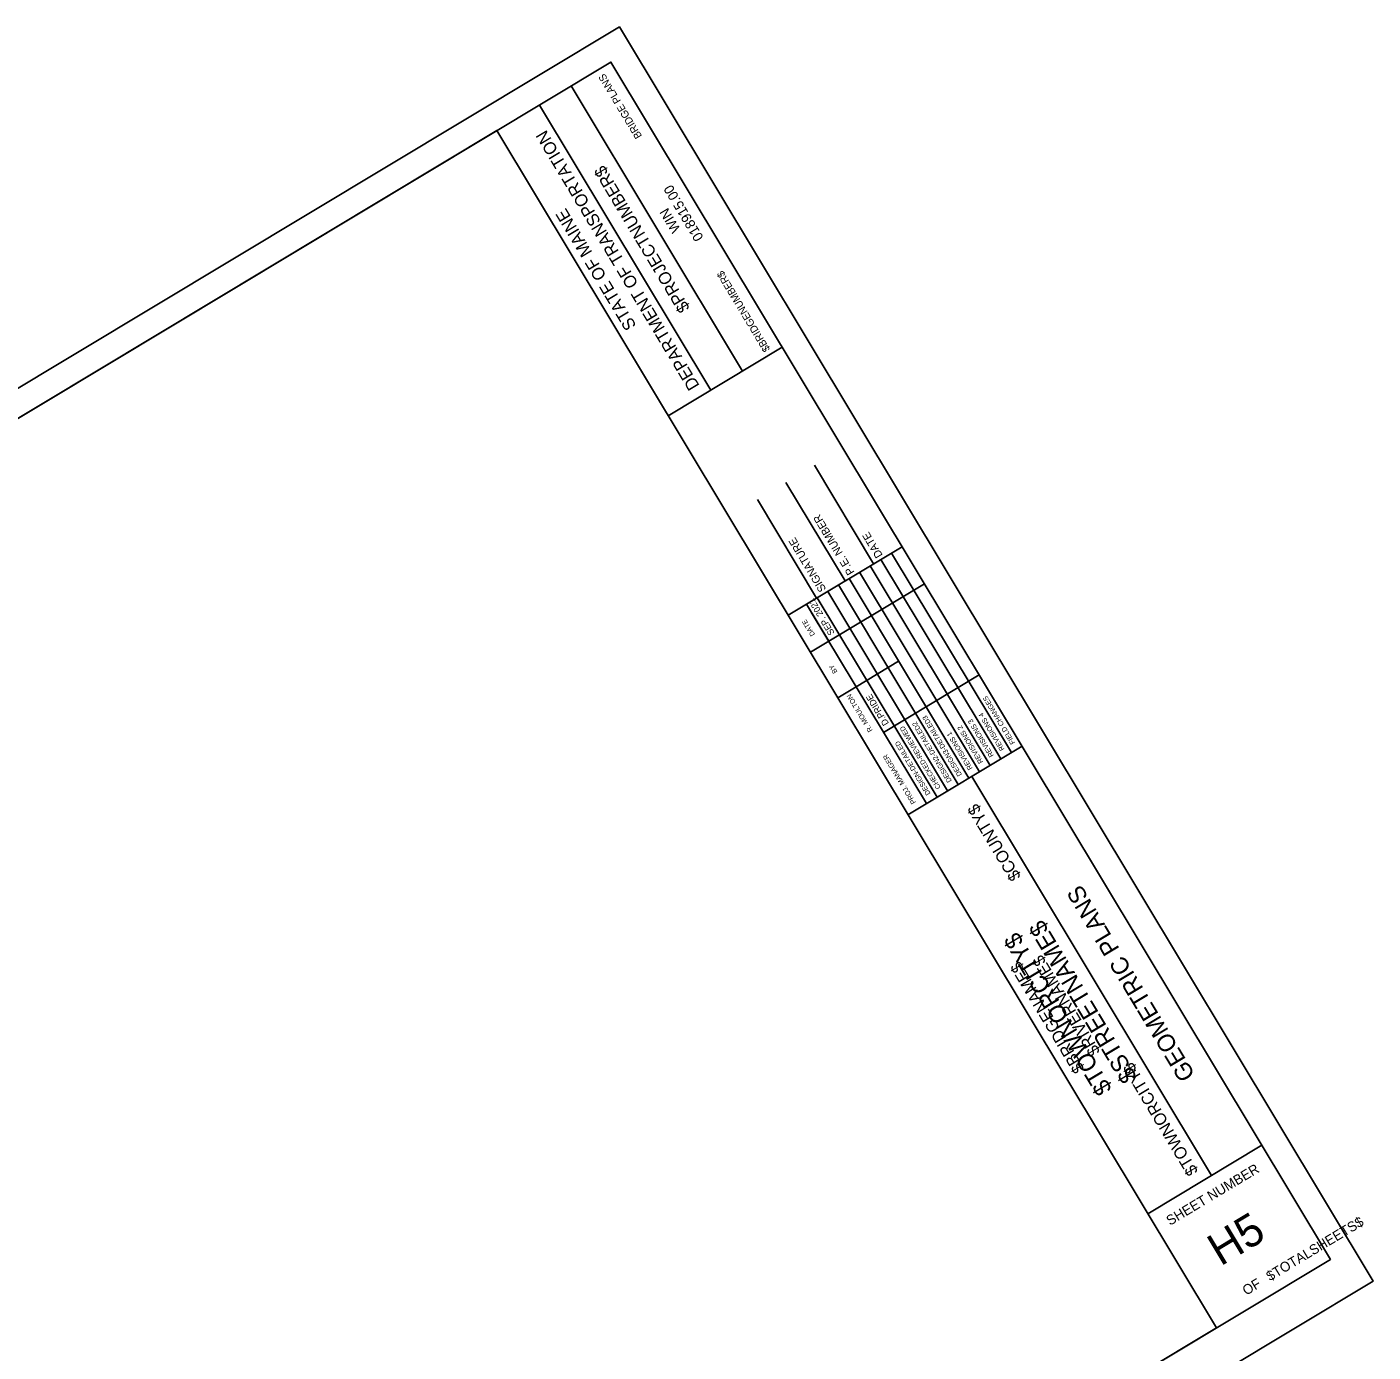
# Model space of a CAD drawing. Extents: x 1744490 to 1745501, y 462969 to 463878.
# Drawn here: x 1744996 to 1745501, y 463380 to 463878 of the extents above; entities that cross this region are included whole.
import ezdxf

# ---------------------------------------------------------------- set-up
doc = ezdxf.new("R2010")
doc.units = 0
for name, color, linetype in [('ANNOTATION', 7, 'Continuous'), ('D_Roadway_Centerline_Flags', 7, 'Continuous'), ('D_Roadway_Centerline_Text', 7, 'Continuous'), ('M_Fencing', 7, 'Continuous'), ('M_Misc_MiscItems', 7, 'Continuous')]:
    doc.layers.add(name, color=color, linetype=linetype)

msp = doc.modelspace()

# ---------------------------------------------------------------- linework, layer by layer
at = {"layer": 'D_Roadway_Centerline_Text'}
for p, q in [((1745264.5, 463749.09), (1745200.12, 463856.24)), ((1745252.52, 463741.9), (1745188.14, 463849.04)), ((1745442.55, 463389.44), (1745172.15, 463839.45)), ((1745236.55, 463732.28), (1745279.41, 463758.03)), ((1745313.73, 463676.63), (1745291.46, 463713.69)), ((1745303.02, 463670.19), (1745280.75, 463707.25)), ((1745292.3, 463663.76), (1745270.04, 463700.82)), ((1745281.59, 463657.32), (1745324.45, 463683.07)), ((1745326.66, 463582.32), (1745369.51, 463608.07)), ((1745440.75, 463446.71), (1745350.62, 463596.71)), ((1745416.79, 463432.31), (1745459.65, 463458.06))]:
    msp.add_line(p, q, dxfattribs=at)
msp.add_lwpolyline([(1744529.28, 463453.17), (1745215.01, 463865.2), (1745485.41, 463415.19), (1744799.67, 463003.16)], close=True, dxfattribs=at)
for points in [[(1745361.52, 463603.28), (1745316.47, 463678.27)], [(1745365.52, 463605.68), (1745320.46, 463680.67)], [(1745353.54, 463598.49), (1745308.48, 463673.47)], [(1745357.53, 463600.88), (1745312.47, 463675.87)], [(1745289.96, 463643.39), (1745332.82, 463669.14)], [(1745296.5, 463666.28), (1745341.56, 463591.29)], [(1745345.55, 463593.69), (1745300.49, 463668.68)], [(1745349.54, 463596.09), (1745304.49, 463671.08)], [(1745296.88, 463647.55), (1745288.51, 463661.48)], [(1745337.57, 463588.89), (1745292.51, 463663.88)], [(1745333.57, 463586.49), (1745290.33, 463658.45)], [(1745307.18, 463630.4), (1745323.15, 463640)], [(1745317.48, 463613.26), (1745353.42, 463634.85)], [(1745300.26, 463626.25), (1745307.18, 463630.41)]]:
    msp.add_lwpolyline(points, dxfattribs=at)
at = {"layer": 'M_Fencing'}
msp.add_lwpolyline([(1744772.86, 462969.21), (1745501.45, 463406.99), (1745218.18, 463878.43), (1744489.59, 463440.65)], close=True, dxfattribs=at)
at = {"layer": 'M_Misc_MiscItems'}
msp.add_lwpolyline([(1744529.28, 463453.17), (1745172.15, 463839.45), (1745442.55, 463389.44), (1744799.67, 463003.16)], close=True, dxfattribs=at)

# ---------------------------------------------------------------- texts
at = {"layer": 'ANNOTATION'}
for s, height, p in [('BRIDGE PLANS', 2.795, (1745226.79, 463837.43)), ('$BRIDGENUMBER$', 2.795, (1745274.93, 463757.31)), ('$COUNTY$', 4.536, (1745369.29, 463559.12)), ('$RIVERNAME$', 4.5358, (1745399.06, 463493.31)), ('$BRIDGENAME$', 4.5358, (1745393.19, 463486.78)), ('$TOWNORCITY$', 4.5358, (1745435.88, 463448.3))]:
    msp.add_text(s, height=height, rotation=121, dxfattribs=at).set_placement(p)
at = {"layer": 'D_Roadway_Centerline_Flags'}
for s, p in [('$STREETNAME$', (1745412.99, 463483.86)), ('$TOWNORCITY$', (1745403.58, 463479.26))]:
    msp.add_text(s, height=6.5214, rotation=121, dxfattribs=at).set_placement(p)
at = {"layer": 'D_Roadway_Centerline_Text'}
for s, height, rotation, p in [('DEPARTMENT OF TRANSPORTATION', 4.6588, 121, (1745248.46, 463743.59)), ('$PROJECTNUMBER$', 4.6588, 121, (1745244.84, 463772.76)), ('018915.00', 3.726, 121, (1745249.94, 463799.27)), ('STATE OF MAINE', 4.6588, 121, (1745224.71, 463766.11)), ('WIN', 3.726, 121, (1745241.28, 463802.42)), ('P.E. NUMBER', 2.9528, 121, (1745306.64, 463673.49)), ('SIGNATURE', 2.953, 121, (1745296.01, 463667.1)), ('DATE', 2.953, 121, (1745317.27, 463679.88)), ('SEP. 2021', 2.423, 121, (1745299.15, 463650.64)), ('DATE', 1.857, 121, (1745291.8, 463650.07)), ('BY', 1.857, 121, (1745300.22, 463636.05)), ('R. MOULTON', 1.864, 121, (1745313.44, 463614.06)), ('D.PRIDE', 2.423, 121, (1745319.56, 463616.68)), ('FIELD CHANGES', 1.8637, 121, (1745366.98, 463609.39)), ('DESIGN2-DETAILED2', 1.8637, 121, (1745343.18, 463595.09)), ('DESIGN3-DETAILED3', 1.8637, 121, (1745347.02, 463597.4)), ('REVISIONS 2', 1.8637, 121, (1745355, 463602.2)), ('REVISIONS 3', 1.8637, 121, (1745359, 463604.59)), ('REVISIONS 4', 1.8637, 121, (1745362.99, 463606.99)), ('CHECKED-REVIEWED', 1.8637, 121, (1745339.03, 463592.6)), ('REVISIONS 1', 1.8637, 121, (1745351.01, 463599.8)), ('DESIGN-DETAILED', 1.8637, 121, (1745335.2, 463590.3)), ('PROJ. MANAGER', 1.8637, 121, (1745329.7, 463586.99)), ('GEOMETRIC PLANS', 6.5214, 121, (1745434.78, 463484.54)), ('SHEET NUMBER', 3.7264, 31, (1745425.14, 463427.78)), ('H5', 12.097, 31, (1745444.13, 463412.45)), ('$TOTALSHEETS$', 3.7264, 31, (1745462.72, 463406.89)), ('OF', 3.726, 31, (1745453.77, 463401.51))]:
    msp.add_text(s, height=height, rotation=rotation, dxfattribs=at).set_placement(p)

doc.saveas('drawing.dxf')
